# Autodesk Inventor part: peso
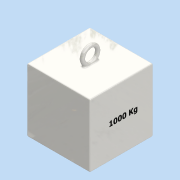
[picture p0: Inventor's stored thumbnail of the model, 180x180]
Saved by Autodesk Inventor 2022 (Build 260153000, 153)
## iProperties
Created: 2022-10
Part Number: peso
Material: Acciaio
Document SubType Name: Modeling
Designer: x300
Density: 7.85 g/cm^3
Appearance: Acciaio
Mass: 982773 g
Surface Area: 15224.8 cm^2
Volume: 125194 cm^3
Author: x300
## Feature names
1. Sweep1
2. Estrusione1 [Extrusion]
3. Raccordo1 [Fillet]
4. Raccordo2 [Fillet]
## Parameters: d3 = 0, d4 = 0, d9 = 0
